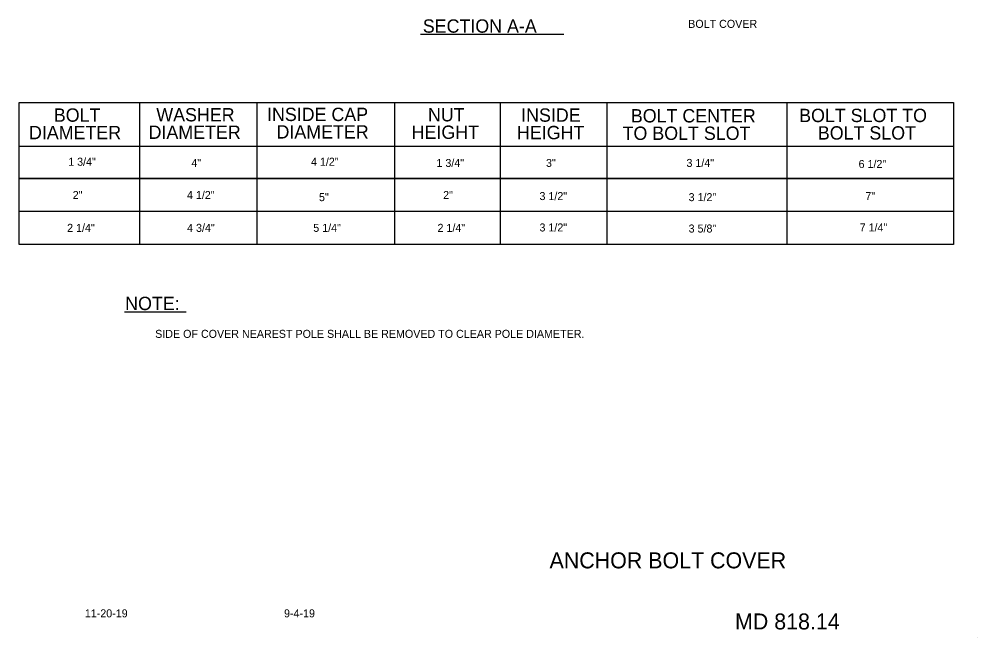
# Model space of a CAD drawing. Extents: x 12.4 to 19.6, y 6 to 16.1.
# Drawn here: x 12.43 to 19.62, y 5.98 to 10.63 of the extents above; entities that cross this region are included whole.
import ezdxf

# ---------------------------------------------------------------- set-up
doc = ezdxf.new("R2010")
doc.units = 0
for name, color, linetype in [('DETL-NOTE', 7, 'Continuous'), ('DETL-TITL', 7, 'Continuous'), ('TTLB-TEXT', 7, 'Continuous')]:
    doc.layers.add(name, color=color, linetype=linetype)

msp = doc.modelspace()

# ---------------------------------------------------------------- linework, layer by layer
at = {"layer": 'DETL-NOTE'}
for p, q in [((12.4323, 8.9349), (12.4323, 10.0009)), ((12.4323, 10.0009), (19.4393, 10.0009)), ((19.4393, 8.9349), (12.4323, 8.9349)), ((13.2213, 8.4306), (13.6847, 8.4306))]:
    msp.add_line(p, q, dxfattribs=at)
for points in [[(13.3343, 10.0009), (13.3343, 8.9349)], [(14.2153, 10.0009), (14.2153, 8.9349)], [(15.2463, 10.0009), (15.2463, 8.9349)], [(16.0383, 10.0009), (16.0383, 8.9349)], [(16.8393, 10.0009), (16.8393, 8.9349)], [(18.1893, 10.0009), (18.1893, 8.9349)], [(19.4393, 10.0009), (19.4393, 8.9349)], [(12.4323, 9.6739), (19.4393, 9.6739)], [(12.4323, 9.4289), (19.4393, 9.4289)], [(19.4393, 9.4289), (12.4323, 9.4289)], [(12.4323, 9.1839), (19.4393, 9.1839)]]:
    msp.add_lwpolyline(points, dxfattribs=at)
at = {"layer": 'DETL-TITL'}
msp.add_line((15.4424, 10.5117), (16.5165, 10.5117), dxfattribs=at)
at = {"layer": 'TTLB-TEXT'}
msp.add_line((19.6208, 5.9844), (19.6208, 5.9844), dxfattribs=at)

# ---------------------------------------------------------------- texts
at = {"layer": 'DETL-NOTE'}
for s, height, p in [('BOLT COVER', 0.06, (17.449, 10.5602)), ('BOLT', 0.1, (12.6921, 9.8559)), ('WASHER', 0.1, (13.4606, 9.8585)), ('INSIDE CAP', 0.1, (14.2908, 9.8611)), ('NUT', 0.1, (15.4973, 9.8585)), ('INSIDE', 0.1, (16.1965, 9.8559)), ('BOLT CENTER', 0.1, (17.0191, 9.8507)), ('BOLT SLOT TO', 0.1, (18.281, 9.8533)), ('DIAMETER', 0.1, (12.5058, 9.7248)), ('DIAMETER', 0.1, (13.4026, 9.7274)), ('DIAMETER', 0.1, (14.362, 9.73)), ('HEIGHT', 0.1, (15.3752, 9.7274)), ('HEIGHT', 0.1, (16.1651, 9.7248)), ('TO BOLT SLOT', 0.1, (16.9572, 9.7196)), ('BOLT SLOT', 0.1, (18.4213, 9.7222)), ('1 3/4"', 0.06, (12.7999, 9.5259)), ('4"', 0.06, (13.7235, 9.5169)), ('4 1/2"', 0.06, (14.6206, 9.5259)), ('1 3/4"', 0.06, (15.5614, 9.5169)), ('3"', 0.06, (16.3828, 9.5169)), ('3 1/4"', 0.06, (17.4361, 9.5169)), ('6 1/2"', 0.06, (18.7267, 9.5089)), ('2"', 0.06, (12.8339, 9.2762)), ('4 1/2"', 0.06, (13.6905, 9.2762)), ('5"', 0.06, (14.6806, 9.2602)), ('2"', 0.06, (15.6114, 9.2762)), ('3 1/2"', 0.06, (16.3338, 9.2682)), ('3 1/2"', 0.06, (17.4521, 9.2602)), ('7"', 0.06, (18.7777, 9.2682)), ('2 1/4"', 0.06, (12.7919, 9.0299)), ('4 3/4"', 0.06, (13.6915, 9.0299)), ('5 1/4"', 0.06, (14.6376, 9.0299)), ('2 1/4"', 0.06, (15.5694, 9.0299)), ('3 1/2"', 0.06, (16.3338, 9.0329)), ('3 5/8"', 0.06, (17.4521, 9.0249)), ('7 1/4"', 0.06, (18.7347, 9.0329)), ('NOTE:', 0.1, (13.2271, 8.4428)), ('SIDE OF COVER NEAREST POLE SHALL BE REMOVED TO CLEAR POLE DIAMETER.', 0.06, (13.4521, 8.2348))]:
    msp.add_text(s, height=height, dxfattribs=at).set_placement(p)
at = {"layer": 'DETL-TITL'}
msp.add_text('SECTION A-A', height=0.100002, dxfattribs=at).set_placement((15.4589, 10.5239))
at = {"layer": 'TTLB-TEXT'}
for s, height, p in [('ANCHOR BOLT COVER', 0.12, (16.4093, 6.5056)), ('11-20-19', 0.06, (12.9246, 6.1381)), ('9-4-19', 0.06, (14.4184, 6.1381)), ('MD 818.14', 0.12, (17.8, 6.0472))]:
    msp.add_text(s, height=height, dxfattribs=at).set_placement(p)

doc.saveas('drawing.dxf')
